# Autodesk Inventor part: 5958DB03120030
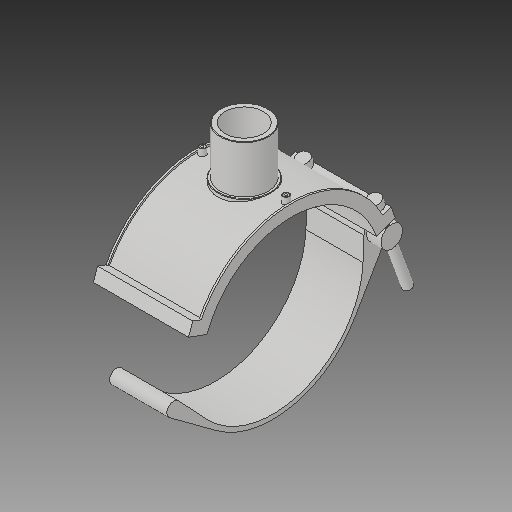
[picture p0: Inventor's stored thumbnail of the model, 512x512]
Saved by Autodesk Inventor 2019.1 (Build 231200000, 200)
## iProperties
Created: 2017-07
Part Number: 5958DB03120030
Material: Generic
Description: PLASSON BRANCH SADDLE 12''DIPS x 3''IPS
Document SubType Name: Modeling
Designer: KIM
Mass: 764.267 g
Surface Area: 1930.38 cm^2
Volume: 764.267 cm^3
Density: 1 g/cm^3
Appearance: Default
Author: KIM
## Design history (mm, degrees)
derived "5958D (2).ipt"
feature "Solid6::5958D (2).ipt"
tag "TaggingFeature1"
body "Solid1"
other parameters: "d_" = 333.8, "d1" = 88.7, "B_" = 180.594, "H_" = 106.934, "H1" = 88.646, "L" = 176.022, "t" = 6, "d244" = 333.8, "d245" = 18.288, "d248" = 180.594, "d249" = 90.297, "d252" = 166.9, "d254" = 18.288, "d256" = 541.782, "d257" = 41.725, "d258" = 270.891, "d259" = 0.5, "d260" = 176.022, "d261" = 0, "d287" = 185.91952, "d288" = 97.57, "d290" = 0, "d291" = 273.834, "d292" = 88.7, "d294" = 0, "d309" = 196.9, "d310" = 12, "d311" = 12, "d315" = 3 deg, "d316" = 4, "d318" = 4, "d320" = 14, "d321" = 0, "d331" = 0.887, "d332" = 70.96, "d334" = 0, "d337" = 0.887, "d340" = 10.56132, "d341" = 10.56132, "d342" = 20 deg, "d343" = 20 deg, "d344" = 722.376, "d345" = 333.8, "d347" = 0, "d352" = 36.576, "d353" = 23.366, "d355" = 0, "d356" = 20 deg, "d357" = 50.07, "d358" = 333.8, "d359" = 350.49, "d360" = 40.056, "d361" = 10 deg, "d362" = 8.13816, "d363" = 66.76, "d366" = 183.59, "d367" = 8.50392, "d368" = 105.6132, "d369" = 0, "d370" = 158.4198, "d371" = 0, "d372" = 132.0165, "d374" = 16.69, "d375" = 23.366, "d376" = 16.69, "d377" = 23.366, "d378" = 166.9, "d379" = 0, "d380" = 14.0196, "d381" = 0, "d383" = 194.332, "d384" = 17.6022, "d385" = 3.338, "d386" = 3.52044, "d387" = 0, "d389" = 360 deg
